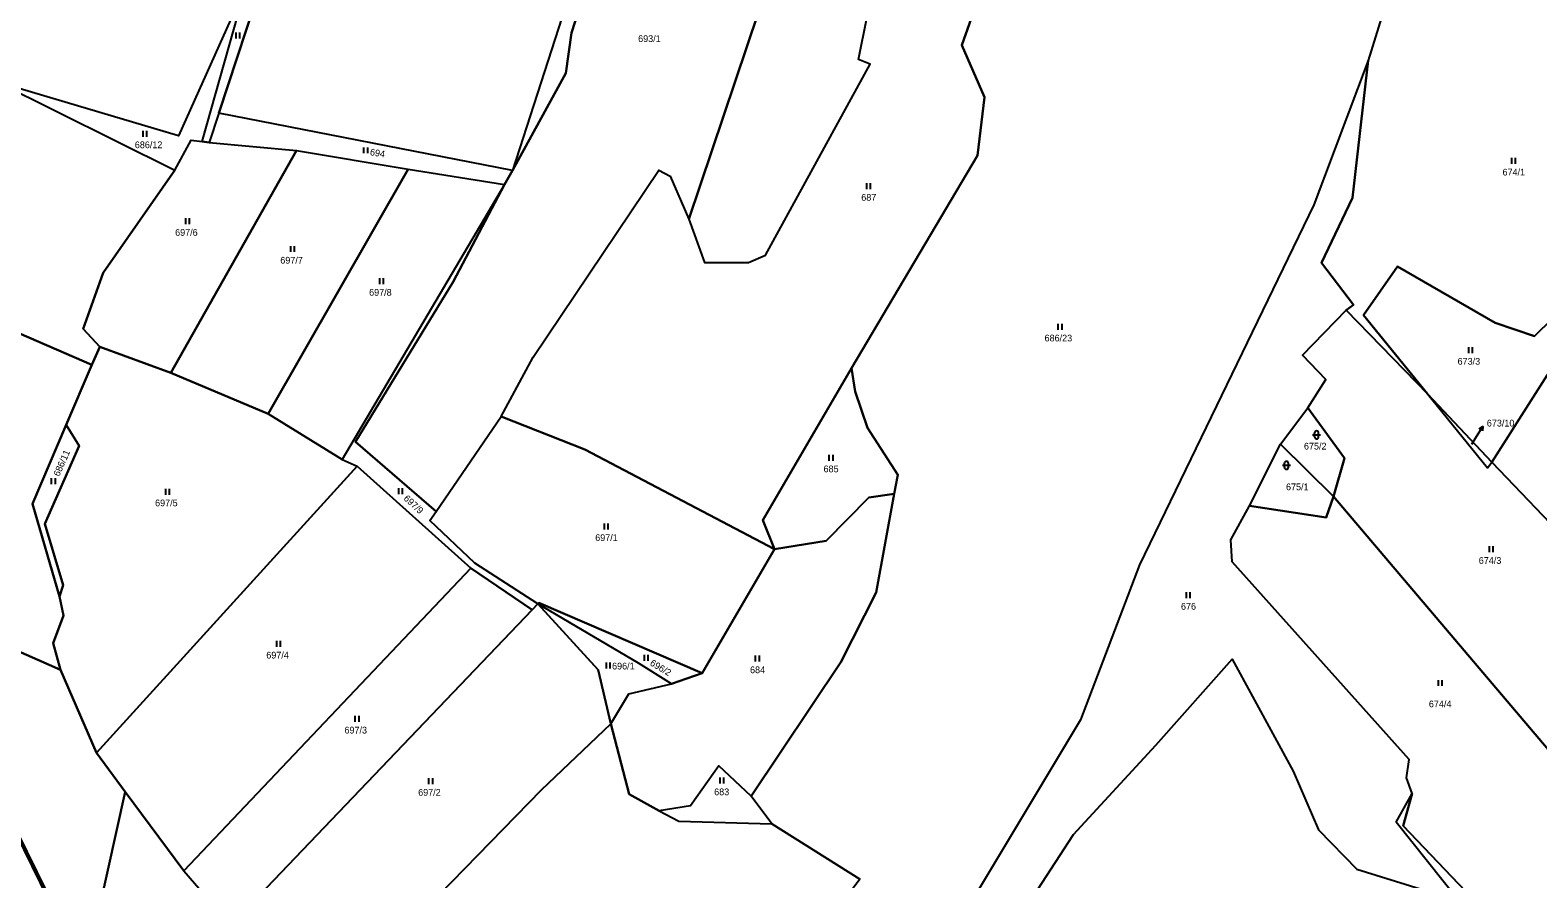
# Model space of a CAD drawing. Extents: x -654083 to -650132, y -1099819 to -1096699.
# Drawn here: x -652523.2 to -652143, y -1099244.9 to -1099030.8 of the extents above; entities that cross this region are included whole.
import ezdxf

# ---------------------------------------------------------------- set-up
doc = ezdxf.new("R2010")
doc.units = 0
for name, color, linetype in [('Obvody jako plochy', 7, 'Continuous'), ('Ostatní hranice', 7, 'Continuous'), ('Parcelní čísla', 7, 'Continuous'), ('Prvky pro prodl_ par_ č_', 7, 'Continuous'), ('Značky kultur', 7, 'Continuous')]:
    doc.layers.add(name, color=color, linetype=linetype)

msp = doc.modelspace()

# ---------------------------------------------------------------- linework, layer by layer
at = {"layer": 'Obvody jako plochy'}
for points in [[(-652468.54, -1099018.95), (-652485.76, -1099057.5), (-652531.41, -1099043.9), (-652573.02, -1099023.24), (-652571.06, -1099007.16), (-652557.25, -1098960.25), (-652560.16, -1098960.22), (-652534.46, -1098936.04), (-652506.83, -1098929.73), (-652411.98, -1098946.66), (-652440.79, -1098966.74), (-652456.94, -1098995.42)], [(-652370.31, -1098969.31), (-652401.59, -1099066.2), (-652475.65, -1099051.75), (-652464.12, -1099016.72)], [(-652324.84, -1098982.48), (-652333.99, -1098979.85), (-652334.16, -1098980.39), (-652359.09, -1098974.01), (-652358.77, -1098972.72), (-652366.99, -1098970.36), (-652386.67, -1099031.49), (-652388.12, -1099041.66), (-652401.59, -1099066.2), (-652403.54, -1099069.73), (-652416.56, -1099094.27), (-652441.19, -1099134.66), (-652420.82, -1099152.23), (-652404.39, -1099128.32), (-652396.36, -1099113.3), (-652364.65, -1099066.13), (-652361.8, -1099067.69), (-652357.11, -1099078.48)], [(-652366.99, -1098970.36), (-652370.31, -1098969.31), (-652401.59, -1099066.2), (-652388.12, -1099041.66), (-652386.67, -1099031.49)], [(-652314.32, -1099038.23), (-652309.99, -1099016.81), (-652289.89, -1098981.76), (-652292.69, -1098978.82), (-652302.93, -1098988.79), (-652324.84, -1098982.48), (-652357.11, -1099078.48), (-652353.16, -1099089.43), (-652342, -1099089.44), (-652337.74, -1099087.59), (-652311.37, -1099039.42)], [(-652284.25, -1099062.43), (-652316.05, -1099116.1), (-652338.43, -1099154.42), (-652335.48, -1099161.76), (-652383.31, -1099136.62), (-652404.39, -1099128.32), (-652396.36, -1099113.3), (-652364.65, -1099066.13), (-652361.8, -1099067.69), (-652357.11, -1099078.48), (-652353.16, -1099089.43), (-652342, -1099089.44), (-652337.74, -1099087.59), (-652311.37, -1099039.42), (-652314.32, -1099038.23), (-652309.99, -1099016.81), (-652289.89, -1098981.76), (-652277.74, -1098985.1), (-652280.6, -1099012.87), (-652288.24, -1099034.57), (-652282.54, -1099047.7)], [(-652486.72, -1099066.1), (-652504.77, -1099092.04), (-652509.84, -1099106.19), (-652505.66, -1099110.73), (-652507.62, -1099115.29), (-652573.21, -1099086.81), (-652590.85, -1099053.87), (-652595.51, -1099042.32), (-652598.64, -1099030.86), (-652611.41, -1099027.66), (-652604.75, -1099007.48), (-652573.02, -1099023.24), (-652574, -1099031.22), (-652531.41, -1099043.9)], [(-652468.54, -1099018.95), (-652464.12, -1099016.72), (-652475.65, -1099051.75), (-652478.08, -1099059.13), (-652479.79, -1099058.92)], [(-652482.57, -1099058.59), (-652479.79, -1099058.92), (-652468.54, -1099018.95), (-652485.76, -1099057.5), (-652531.41, -1099043.9), (-652486.72, -1099066.1)], [(-652401.59, -1099066.2), (-652475.65, -1099051.75), (-652478.08, -1099059.13), (-652456.05, -1099061.14), (-652427.89, -1099065.89), (-652403.54, -1099069.73)], [(-652478.08, -1099059.13), (-652456.05, -1099061.14), (-652487.75, -1099117.3), (-652505.66, -1099110.73), (-652509.84, -1099106.19), (-652504.77, -1099092.04), (-652486.72, -1099066.1), (-652482.57, -1099058.59), (-652479.79, -1099058.92)], [(-652427.89, -1099065.89), (-652463.22, -1099127.62), (-652487.75, -1099117.3), (-652456.05, -1099061.14)], [(-652427.89, -1099065.89), (-652403.54, -1099069.73), (-652444.52, -1099139.1), (-652463.22, -1099127.62)], [(-652441.19, -1099134.66), (-652416.56, -1099094.27), (-652403.54, -1099069.73), (-652444.52, -1099139.1), (-652440.72, -1099140.81), (-652412.06, -1099166.56), (-652396.6, -1099177.05), (-652395.13, -1099175.53), (-652411.09, -1099165.3), (-652422.39, -1099154.51), (-652420.82, -1099152.23)], [(-652522.65, -1099150.36), (-652515.84, -1099173.67), (-652514.77, -1099178.52), (-652517.37, -1099185.51), (-652515.51, -1099192.22), (-652575.68, -1099165.7), (-652574.76, -1099160.43), (-652573.92, -1099155.92), (-652568.69, -1099145.34), (-652564.38, -1099126.87), (-652561.79, -1099126.66), (-652561.52, -1099122.92), (-652572.78, -1099092.57), (-652573.21, -1099086.81), (-652507.62, -1099115.29), (-652514.11, -1099130.38)], [(-652186.91, -1099102.76), (-652170.81, -1099122.59), (-652154.56, -1099139.81), (-652133.11, -1099106.1), (-652139.3, -1099103.56), (-652143.84, -1099107.98), (-652153.74, -1099104.66), (-652178.4, -1099090.47)], [(-652116.6, -1099189.03), (-652121.36, -1099214.98), (-652126.27, -1099228.98), (-652194.52, -1099148.49), (-652191.7, -1099138.82), (-652201.02, -1099126.06), (-652196.43, -1099118.98), (-652202.31, -1099112.81), (-652191.27, -1099101.48), (-652170.81, -1099122.59), (-652155.65, -1099141.25), (-652154.56, -1099139.81), (-652114.06, -1099182.2)], [(-652440.72, -1099140.81), (-652506.44, -1099213.13), (-652515.51, -1099192.22), (-652517.37, -1099185.51), (-652514.77, -1099178.52), (-652515.84, -1099173.67), (-652514.91, -1099170.88), (-652519.48, -1099155.38), (-652510.88, -1099135.72), (-652514.11, -1099130.38), (-652507.62, -1099115.29), (-652505.66, -1099110.73), (-652487.75, -1099117.3), (-652463.22, -1099127.62), (-652444.52, -1099139.1)], [(-652312.06, -1099131.14), (-652304.41, -1099143.04), (-652305.27, -1099147.78), (-652311.67, -1099148.73), (-652322.45, -1099159.69), (-652335.48, -1099161.76), (-652338.43, -1099154.42), (-652316.05, -1099116.1), (-652315.18, -1099122.01)], [(-652170.81, -1099122.59), (-652155.65, -1099141.25), (-652154.56, -1099139.81)], [(-652394.9, -1099175.31), (-652395.13, -1099175.53), (-652411.09, -1099165.3), (-652422.39, -1099154.51), (-652420.82, -1099152.23), (-652404.39, -1099128.32), (-652383.31, -1099136.62), (-652335.48, -1099161.76), (-652353.74, -1099193.05)], [(-652201.02, -1099126.06), (-652191.7, -1099138.82), (-652194.52, -1099148.49), (-652207.85, -1099135.29)], [(-652510.88, -1099135.72), (-652519.48, -1099155.38), (-652514.91, -1099170.88), (-652515.84, -1099173.67), (-652522.65, -1099150.36), (-652514.11, -1099130.38)], [(-652196.36, -1099153.76), (-652215.73, -1099150.82), (-652207.85, -1099135.29), (-652194.52, -1099148.49)], [(-652412.06, -1099166.56), (-652484.46, -1099242.95), (-652499.28, -1099223.01), (-652506.44, -1099213.13), (-652440.72, -1099140.81)], [(-652309.82, -1099172.68), (-652318.76, -1099190.29), (-652341.39, -1099224.08), (-652349.52, -1099216.43), (-652356.63, -1099226.48), (-652364.58, -1099227.8), (-652372.17, -1099223.55), (-652376.74, -1099205.82), (-652372.22, -1099198.27), (-652361.48, -1099195.73), (-652353.74, -1099193.05), (-652335.48, -1099161.76), (-652322.45, -1099159.69), (-652311.67, -1099148.73), (-652305.27, -1099147.78)], [(-652128, -1099241.08), (-652145.4, -1099264.61), (-652176.96, -1099231.56), (-652174.69, -1099223.44), (-652176.11, -1099219.43), (-652175.42, -1099214.85), (-652220.02, -1099164.97), (-652220.42, -1099159.39), (-652215.73, -1099150.82), (-652196.36, -1099153.76), (-652194.52, -1099148.49), (-652126.27, -1099228.98), (-652123.09, -1099232.42)], [(-652506.44, -1099213.13), (-652499.28, -1099223.01), (-652510.05, -1099271.98), (-652514.38, -1099258.69), (-652526.81, -1099233.31), (-652578.49, -1099226.63), (-652597.86, -1099230.9), (-652611.34, -1099231.19), (-652635.14, -1099211.6), (-652658.12, -1099219.17), (-652640.83, -1099206.43), (-652634, -1099174.58), (-652631.58, -1099170.53), (-652604.08, -1099175.4), (-652597.09, -1099179.93), (-652569.1, -1099185.2), (-652575.68, -1099165.7), (-652515.51, -1099192.22)], [(-652396.6, -1099177.05), (-652412.06, -1099166.56), (-652484.46, -1099242.95), (-652472.63, -1099256.64)], [(-652445.73, -1099275.28), (-652394.22, -1099222.51), (-652376.74, -1099205.82), (-652379.92, -1099192.22), (-652395.13, -1099175.53), (-652396.6, -1099177.05), (-652472.63, -1099256.64), (-652446.81, -1099277.48)], [(-652353.74, -1099193.05), (-652361.48, -1099195.73), (-652369.82, -1099190.48), (-652395.13, -1099175.53), (-652394.9, -1099175.31)], [(-652361.48, -1099195.73), (-652369.82, -1099190.48), (-652395.13, -1099175.53), (-652379.92, -1099192.22), (-652376.74, -1099205.82), (-652372.22, -1099198.27)], [(-652151, -1099265.12), (-652179.1, -1099291.89), (-652203.69, -1099308.4), (-652250.94, -1099291.91), (-652266.93, -1099283), (-652286.97, -1099264.69), (-652275.85, -1099252.86), (-652273.66, -1099254.73), (-652260.09, -1099233.71), (-652239.29, -1099211.22), (-652220.07, -1099189.52), (-652204.7, -1099217.8), (-652198.3, -1099232.6), (-652188.62, -1099242.46), (-652162.89, -1099250.49)], [(-652359.58, -1099230.41), (-652336.13, -1099231.04), (-652313.96, -1099245.04), (-652322.03, -1099255.9), (-652363.72, -1099309.07), (-652373.09, -1099303.5), (-652383.82, -1099299.66), (-652398.56, -1099299.76), (-652421.43, -1099297.24), (-652448.23, -1099285.84), (-652449.24, -1099284.87), (-652450.4, -1099283.75), (-652446.81, -1099277.48), (-652445.73, -1099275.28), (-652394.22, -1099222.51), (-652376.74, -1099205.82), (-652372.17, -1099223.55), (-652364.58, -1099227.8)], [(-652341.39, -1099224.08), (-652349.52, -1099216.43), (-652356.63, -1099226.48), (-652364.58, -1099227.8), (-652359.58, -1099230.41), (-652336.13, -1099231.04)], [(-652499.28, -1099223.01), (-652484.46, -1099242.95), (-652472.63, -1099256.64), (-652446.81, -1099277.48), (-652450.4, -1099283.75), (-652449.24, -1099284.87), (-652451.6, -1099287.25), (-652451.52, -1099327.06), (-652451.53, -1099339.85), (-652469.54, -1099331.17), (-652485.78, -1099323.2), (-652498.39, -1099305.75), (-652503.41, -1099292.36), (-652510.05, -1099271.98)], [(-652161.05, -1099251.15), (-652162.89, -1099250.49), (-652178.71, -1099230.66), (-652174.69, -1099223.44), (-652176.96, -1099231.56), (-652145.4, -1099264.61), (-652146.06, -1099267.37), (-652149.62, -1099263.81)]]:
    msp.add_lwpolyline(points, close=True, dxfattribs=at)
for points in [[(-652140.54, -1098997.91), (-652149.35, -1099002.46), (-652156.43, -1098996.68), (-652171.74, -1099009.98), (-652175.32, -1099004.71), (-652185.76, -1099038.47), (-652189.75, -1099073.15), (-652197.55, -1099089.52), (-652189.47, -1099100.09), (-652191.27, -1099101.48), (-652170.81, -1099122.59), (-652186.91, -1099102.76), (-652178.4, -1099090.47), (-652153.74, -1099104.66), (-652143.84, -1099107.98), (-652139.3, -1099103.56)], [(-652175.32, -1099004.71), (-652185.76, -1099038.47), (-652199.5, -1099074.9), (-652243.4, -1099165.75), (-652258.34, -1099204.81), (-652291.84, -1099260.77)], [(-652313.96, -1099245.04), (-652336.13, -1099231.04), (-652341.39, -1099224.08), (-652318.76, -1099190.29), (-652309.82, -1099172.68), (-652305.27, -1099147.78), (-652304.41, -1099143.04), (-652312.06, -1099131.14), (-652315.18, -1099122.01), (-652316.05, -1099116.1), (-652284.25, -1099062.43), (-652282.54, -1099047.7), (-652288.24, -1099034.57), (-652280.6, -1099012.87)], [(-652273.66, -1099254.73), (-652260.09, -1099233.71), (-652239.29, -1099211.22), (-652220.07, -1099189.52), (-652204.7, -1099217.8), (-652198.3, -1099232.6), (-652188.62, -1099242.46), (-652162.89, -1099250.49), (-652178.71, -1099230.66), (-652174.69, -1099223.44), (-652176.11, -1099219.43), (-652175.42, -1099214.85), (-652220.02, -1099164.97), (-652220.42, -1099159.39), (-652215.73, -1099150.82), (-652207.85, -1099135.29), (-652201.02, -1099126.06), (-652196.43, -1099118.98), (-652202.31, -1099112.81), (-652191.27, -1099101.48), (-652189.47, -1099100.09), (-652197.55, -1099089.52), (-652189.75, -1099073.15), (-652185.76, -1099038.47), (-652199.5, -1099074.9), (-652243.4, -1099165.75), (-652258.34, -1099204.81), (-652291.84, -1099260.77)], [(-652133.11, -1099106.1), (-652154.56, -1099139.81), (-652114.06, -1099182.2)]]:
    msp.add_lwpolyline(points, dxfattribs=at)
at = {"layer": 'Ostatní hranice'}
msp.add_line((-652513.91, -1099258.51), (-652526.46, -1099232.95), dxfattribs=at)
at = {"layer": 'Prvky pro prodl_ par_ č_'}
for p, q in [((-652158.44, -1099133.35), (-652156.84, -1099130.81)), ((-652159.64, -1099135.26), (-652158.44, -1099133.35))]:
    msp.add_line(p, q, dxfattribs=at)
msp.add_lwpolyline([(-652157.8, -1099131.39), (-652156.84, -1099130.81), (-652156.95, -1099131.92)], dxfattribs=at)
at = {"layer": 'Značky kultur'}
for p, q in [((-652471.37, -1099031.38), (-652471.37, -1099032.88)), ((-652470.34, -1099032.88), (-652470.34, -1099031.38)), ((-652494.77, -1099056.2), (-652494.77, -1099057.7)), ((-652493.74, -1099057.7), (-652493.74, -1099056.2)), ((-652439.1, -1099060.38), (-652439.1, -1099061.88)), ((-652438.08, -1099061.88), (-652438.08, -1099060.38)), ((-652149.6, -1099063.04), (-652149.6, -1099064.54)), ((-652148.58, -1099064.54), (-652148.58, -1099063.04)), ((-652312.31, -1099069.42), (-652312.31, -1099070.92)), ((-652311.29, -1099070.92), (-652311.29, -1099069.42)), ((-652484.06, -1099078.27), (-652484.06, -1099079.77)), ((-652483.04, -1099079.77), (-652483.04, -1099078.27)), ((-652457.58, -1099085.27), (-652457.58, -1099086.77)), ((-652456.56, -1099086.77), (-652456.56, -1099085.27)), ((-652435.12, -1099093.39), (-652435.12, -1099094.89)), ((-652434.09, -1099094.89), (-652434.09, -1099093.39)), ((-652263.99, -1099104.91), (-652263.99, -1099106.41)), ((-652262.96, -1099106.41), (-652262.96, -1099104.91)), ((-652160.48, -1099110.77), (-652160.48, -1099112.27)), ((-652159.45, -1099112.27), (-652159.45, -1099110.77)), ((-652199.26, -1099133.42), (-652199.26, -1099132.42)), ((-652198.26, -1099133.42), (-652198.26, -1099132.42)), ((-652199.76, -1099132.92), (-652197.76, -1099132.92)), ((-652321.74, -1099137.93), (-652321.74, -1099139.43)), ((-652320.71, -1099139.43), (-652320.71, -1099137.93)), ((-652517.87, -1099143.82), (-652517.87, -1099145.32)), ((-652516.84, -1099145.32), (-652516.84, -1099143.82)), ((-652207.38, -1099140.6), (-652205.38, -1099140.6)), ((-652206.88, -1099141.1), (-652206.88, -1099140.1)), ((-652205.88, -1099141.1), (-652205.88, -1099140.1)), ((-652489.08, -1099146.51), (-652489.08, -1099148.01)), ((-652488.06, -1099148.01), (-652488.06, -1099146.51)), ((-652430.28, -1099146.4), (-652430.28, -1099147.9)), ((-652429.26, -1099147.9), (-652429.26, -1099146.4)), ((-652378.43, -1099155.27), (-652378.43, -1099156.77)), ((-652377.41, -1099156.77), (-652377.41, -1099155.27)), ((-652155.22, -1099161.03), (-652155.22, -1099162.53)), ((-652154.2, -1099162.53), (-652154.2, -1099161.03)), ((-652231.7, -1099172.61), (-652231.7, -1099174.11)), ((-652230.68, -1099174.11), (-652230.68, -1099172.61)), ((-652461.07, -1099184.92), (-652461.07, -1099186.42)), ((-652460.05, -1099186.42), (-652460.05, -1099184.92)), ((-652368.37, -1099188.44), (-652368.37, -1099189.94)), ((-652367.34, -1099189.94), (-652367.34, -1099188.44)), ((-652340.32, -1099188.61), (-652340.32, -1099190.11)), ((-652339.3, -1099190.11), (-652339.3, -1099188.61)), ((-652377.97, -1099190.38), (-652377.97, -1099191.88)), ((-652376.95, -1099191.88), (-652376.95, -1099190.38)), ((-652168.1, -1099194.78), (-652168.1, -1099196.28)), ((-652167.08, -1099196.28), (-652167.08, -1099194.78)), ((-652441.29, -1099203.83), (-652441.29, -1099205.33)), ((-652440.27, -1099205.33), (-652440.27, -1099203.83)), ((-652422.71, -1099219.53), (-652422.71, -1099221.03)), ((-652421.69, -1099221.03), (-652421.69, -1099219.53)), ((-652349.29, -1099219.41), (-652349.29, -1099220.91)), ((-652348.27, -1099220.91), (-652348.27, -1099219.41))]:
    msp.add_line(p, q, dxfattribs=at)
for centre, start, end in [((-652198.76, -1099132.42), 0, 180), ((-652198.76, -1099133.42), 180, 0), ((-652206.38, -1099140.1), 0, 180), ((-652206.38, -1099141.1), 180, 0)]:
    msp.add_arc(centre, 0.5, start, end, dxfattribs=at)

# ---------------------------------------------------------------- texts
at = {"layer": 'Parcelní čísla'}
for s, p in [('693/1', (-652369.87, -1099033.8)), ('686/12', (-652496.81, -1099060.59)), ('674/1', (-652151.87, -1099067.48)), ('687', (-652313.6, -1099073.85)), ('697/6', (-652486.64, -1099082.7)), ('697/7', (-652460.12, -1099089.71)), ('697/8', (-652437.72, -1099097.82)), ('686/23', (-652267.37, -1099109.34)), ('673/3', (-652163.21, -1099115.21)), ('675/2', (-652201.96, -1099136.62)), ('685', (-652323.11, -1099142.36)), ('675/1', (-652206.48, -1099146.89)), ('697/5', (-652491.7, -1099150.94)), ('697/1', (-652380.7, -1099159.7)), ('674/3', (-652157.87, -1099165.47)), ('676', (-652232.97, -1099177.05)), ('697/4', (-652463.65, -1099189.35)), ('696/1', (-652376.45, -1099192.11)), ('684', (-652341.65, -1099193.05)), ('674/4', (-652170.45, -1099201.66)), ('697/3', (-652443.94, -1099208.27)), ('697/2', (-652425.35, -1099223.97)), ('683', (-652350.7, -1099223.84))]:
    msp.add_text(s, height=1.7, dxfattribs=at).set_placement(p)
for s, height, rotation, p in [('694', 1.7, 350.901, (-652437.6, -1099062.34)), ('673/10', 0.1, 313.974, (-652159.64, -1099135.26)), ('686/11', 1.7, 66.141, (-652515.88, -1099143.54)), ('697/9', 1.7, 317.295, (-652429.16, -1099149.15)), ('696/2', 1.7, 329.256, (-652367.06, -1099190.94))]:
    msp.add_text(s, height=height, rotation=rotation, dxfattribs=at).set_placement(p)
at = {"layer": 'Prvky pro prodl_ par_ č_'}
msp.add_text('673/10', height=1.7, dxfattribs=at).set_placement((-652155.84, -1099130.81))

doc.saveas('drawing.dxf')
